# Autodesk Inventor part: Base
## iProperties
Created: 2010-01
Part Number: Base
Document SubType Name: Modeling
Designer: jgehrig
Density: 1 g/cm^3
Author: jgehrig
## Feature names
1. Extrusion1
2. Fillet1
3. Shell1
4. Extrusion2
5. Extrusion3
6. Extrusion4
